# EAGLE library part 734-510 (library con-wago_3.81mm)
Serie 734, Federleiste mit geraden Einlötstiften / Series 734, Female connector with straight solder pins Polzahl / Pole No.: 10 Bemessungsspannung / Rated Voltage: 160 V Nennstrom / Nominal Current: 10 A Lötstiftlänge: / Solder Pin Length: 3.8 mm Farbe / Color: orange / orange Stand: 01.01.2012. Die jeweils aktuellen Daten zu diesem Artikel finden Sie in unserem Produktkatalog, den Sie unter www.wago.com einsehen können. As of: 01/01/2012. Please find the newest data for this article in our product catalogue, which can be viewed under www.wago.com.
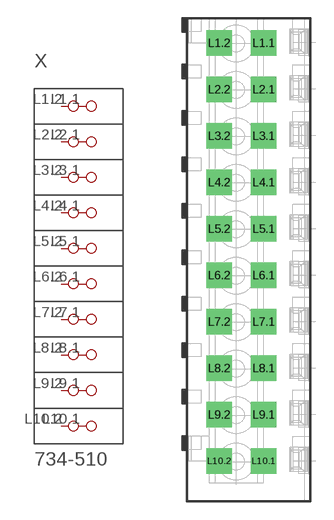
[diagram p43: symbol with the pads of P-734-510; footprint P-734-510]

Designator prefix X

## 734-510  [P-734-510]
L1.1  P1.1
L1.2  P1.2
L2.1  P2.1
L2.2  P2.2
L3.1  P3.1
L3.2  P3.2
L4.1  P4.1
L4.2  P4.2
L5.1  P5.1
L5.2  P5.2
L6.1  P6.1
L6.2  P6.2
L7.1  P7.1
L7.2  P7.2
L8.1  P8.1
L8.2  P8.2
L9.1  P9.1
L9.2  P9.2
L10.1  P10.1
L10.2  P10.2

## Footprint P-734-510 (pad centres in mm)
drill 1.4 square: L1.1 1.189,17.79; L1.2 -2.461,17.79; L2.1 1.189,13.98; L2.2 -2.461,13.98; L3.1 1.189,10.17; L3.2 -2.461,10.17; L4.1 1.189,6.36; L4.2 -2.461,6.36; L5.1 1.189,2.55; L5.2 -2.461,2.55; L6.1 1.189,-1.26; L6.2 -2.461,-1.26; L7.1 1.189,-5.07; L7.2 -2.461,-5.07; L8.1 1.189,-8.88; L8.2 -2.461,-8.88; L9.1 1.189,-12.69; L9.2 -2.461,-12.69; L10.1 1.189,-16.5; L10.2 -2.461,-16.5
